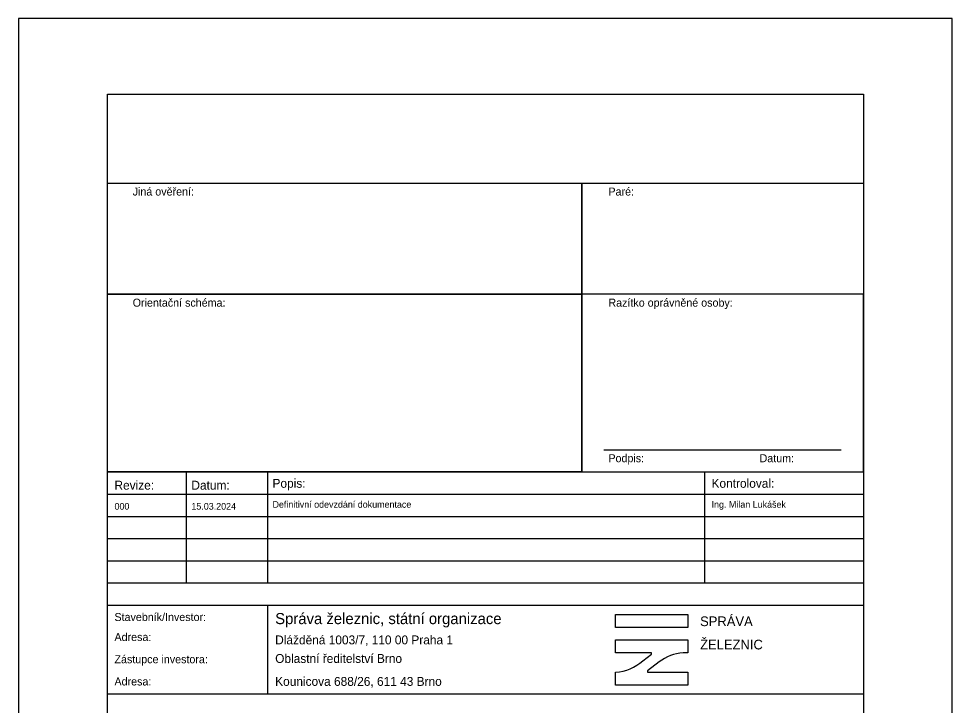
# Model space of a CAD drawing. Extents: x -97.1 to -76.1, y 366.2 to 395.9.
# Drawn here: x -97.06 to -76.06, y 380.5 to 395.95 of the extents above; entities that cross this region are included whole.
import ezdxf

# ---------------------------------------------------------------- set-up
doc = ezdxf.new("R2010")
doc.units = 0
for name, color, linetype in [('Default', 7, 'Continuous'), ('Rozpiska_Logo', 7, 'Continuous'), ('Rozpiska_pola_3', 7, 'Continuous'), ('Rozpiska_pole_1', 7, 'Continuous'), ('Rozpiska_pole_2', 7, 'Continuous'), ('Rozpiska_pole_4', 7, 'Continuous'), ('Rozpiska_pole_5', 7, 'Continuous'), ('Rozpiska_pole_6', 7, 'Continuous')]:
    doc.layers.add(name, color=color, linetype=linetype)

msp = doc.modelspace()

# ---------------------------------------------------------------- linework, layer by layer
at = {"layer": 'Default'}
for p, q in [((-76.063, 395.949), (-97.063, 395.949)), ((-97.063, 395.949), (-97.063, 366.249)), ((-76.063, 366.249), (-76.063, 395.949)), ((-84.398, 385.749), (-84.398, 392.249))]:
    msp.add_line(p, q, dxfattribs=at)
msp.add_lwpolyline([(-97.063, 366.249), (-76.063, 366.249), (-76.063, 395.949), (-97.063, 395.949)], close=True, dxfattribs=at)
at = {"layer": 'Rozpiska_Logo'}
for p, q in [((-83.023, 381.502), (-82.829, 381.648)), ((-82.829, 381.648), (-82.829, 381.683)), ((-82.66, 381.475), (-82.921, 381.273)), ((-82.921, 381.273), (-82.921, 381.242))]:
    msp.add_line(p, q, dxfattribs=at)
msp.add_lwpolyline([(-83.641, 382.54), (-82.011, 382.54), (-82.011, 382.247), (-83.641, 382.247)], close=True, dxfattribs=at)
for points in [[(-82.829, 381.683), (-83.641, 381.683), (-83.641, 381.976), (-82.011, 381.976), (-82.011, 381.683), (-82.118, 381.683)], [(-82.921, 381.242), (-82.011, 381.242), (-82.011, 380.949), (-83.641, 380.949), (-83.641, 381.242), (-83.634, 381.242)]]:
    msp.add_lwpolyline(points, dxfattribs=at)
for centre, radius, start, end in [((-82.044, 380.681), 1.004, 94.2142, 127.7808), ((-83.719, 382.291), 1.052, 274.6014, 311.4254)]:
    msp.add_arc(centre, radius, start, end, dxfattribs=at)
at = {"layer": 'Rozpiska_pola_3'}
msp.add_line((-83.898, 386.249), (-78.563, 386.249), dxfattribs=at)
at = {"layer": 'Rozpiska_pole_1'}
msp.add_lwpolyline([(-95.063, 394.249), (-78.063, 394.249), (-78.063, 367.749), (-95.063, 367.749)], close=True, dxfattribs=at)
at = {"layer": 'Rozpiska_pole_2'}
for points in [[(-95.063, 392.249), (-84.398, 392.249), (-84.398, 389.749), (-95.063, 389.749)], [(-84.398, 392.249), (-78.063, 392.249), (-78.063, 389.749), (-84.398, 389.749)], [(-95.063, 389.749), (-84.398, 389.749), (-84.398, 385.749), (-95.063, 385.749)], [(-78.063, 389.749), (-84.398, 389.749), (-84.398, 385.749), (-78.063, 385.749)]]:
    msp.add_lwpolyline(points, close=True, dxfattribs=at)
at = {"layer": 'Rozpiska_pole_4'}
for p, q in [((-93.285, 383.249), (-93.285, 385.749)), ((-91.458, 383.249), (-91.458, 385.749)), ((-81.633, 383.249), (-81.633, 385.749)), ((-95.063, 385.249), (-78.063, 385.249)), ((-95.063, 384.749), (-78.063, 384.749)), ((-95.063, 384.249), (-78.063, 384.249)), ((-95.063, 383.749), (-78.063, 383.749))]:
    msp.add_line(p, q, dxfattribs=at)
msp.add_lwpolyline([(-95.063, 385.749), (-78.063, 385.749), (-78.063, 383.249), (-95.063, 383.249)], close=True, dxfattribs=at)
at = {"layer": 'Rozpiska_pole_5'}
msp.add_line((-91.458, 380.749), (-91.458, 382.749), dxfattribs=at)
msp.add_lwpolyline([(-95.063, 382.749), (-78.063, 382.749), (-78.063, 380.749), (-95.063, 380.749)], close=True, dxfattribs=at)

# ---------------------------------------------------------------- texts
at = {"layer": 'Rozpiska_pola_3'}
for s, p in [('Paré:', (-83.798, 391.969)), ('Razítko oprávněné osoby:', (-83.798, 389.469)), ('Podpis:', (-83.798, 385.969)), ('Datum:', (-80.398, 385.969))]:
    msp.add_text(s, height=0.18, dxfattribs=at).set_placement(p)
at = {"layer": 'Rozpiska_pole_2'}
for s, p in [('Jiná ověření:', (-94.498, 391.969)), ('Orientační schéma:', (-94.498, 389.469))]:
    msp.add_text(s, height=0.18, dxfattribs=at).set_placement(p)
at = {"layer": 'Rozpiska_pole_4'}
for s, height, p in [('Revize:', 0.2, (-94.908, 385.352)), ('Popis:', 0.2, (-91.353, 385.394)), ('Kontroloval:', 0.2, (-81.478, 385.394)), ('Datum:', 0.2, (-93.178, 385.352)), ('000', 0.15, (-94.908, 384.902)), ('15.03.2024', 0.15, (-93.178, 384.902)), ('Definitivní odevzdání dokumentace', 0.15, (-91.353, 384.944)), ('Ing. Milan Lukášek', 0.15, (-81.478, 384.944))]:
    msp.add_text(s, height=height, dxfattribs=at).set_placement(p)
at = {"layer": 'Rozpiska_pole_5'}
for s, height, p in [('Stavebník/Investor:', 0.18, (-94.908, 382.396)), ('Správa železnic, státní organizace', 0.25, (-91.293, 382.326)), ('Adresa:', 0.18, (-94.908, 381.946)), ('Zástupce investora:', 0.18, (-94.908, 381.446)), ('Adresa:', 0.18, (-94.908, 380.946))]:
    msp.add_text(s, height=height, dxfattribs=at).set_placement(p)
at = {"layer": 'Rozpiska_pole_6'}
for s, height, p in [('SPRÁVA', 0.2183, (-81.736, 382.281)), ('Dlážděná 1003/7, 110 00 Praha 1', 0.2, (-91.293, 381.871)), ('ŽELEZNIC', 0.2183, (-81.736, 381.757)), ('Oblastní ředitelství Brno', 0.2, (-91.293, 381.453)), ('Kounicova 688/26, 611 43 Brno', 0.2, (-91.293, 380.937))]:
    msp.add_text(s, height=height, dxfattribs=at).set_placement(p)

doc.saveas('drawing.dxf')
